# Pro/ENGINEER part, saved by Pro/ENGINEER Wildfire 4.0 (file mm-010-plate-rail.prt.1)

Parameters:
  METRIC = "NO"

Other parameters: PITCH, DRILL_POINT_ANGLE, DRILL_DEPTH, DRILL_DIAMETER, THREAD_DIAMETER, THREADS_PER_INCH, THREAD_DEPTH, THREAD_LENGTH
